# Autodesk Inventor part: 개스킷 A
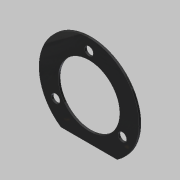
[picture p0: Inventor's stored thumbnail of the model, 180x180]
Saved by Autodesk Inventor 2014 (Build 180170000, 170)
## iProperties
Created: 2020-04
Part Number: 개스킷 A
Material: 고무
Document SubType Name: Modeling
Designer: mduedu
Density: 0.93 g/cm^3
Appearance: Rubber - Black - Version 1.1
Mass: 1.09963 g
Surface Area: 26.6928 cm^2
Volume: 1.18239 cm^3
Author: mduedu
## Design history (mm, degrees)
sketch "스케치1"
  geometry: C1 r 26 at (0, 0); 1 further point
  constraints: 1 centre point, 1 coincident
  dimensions: "d0" = 52 diameter of C1
extrude "돌출1" new body sketch "스케치1" distance "d1" = 1; taper "d2" = 0 deg
sketch "스케치2"
  geometry: L1 (-14.62, -21.5)-(14.62, -21.5); A1 r 26 centre (0, 0) between (-14.62, -21.5) and (14.62, -21.5) reference; 1 further point
  constraints: 2 end point, 2 point on circle, 1 horizontal
  dimensions: "d3" = 21.5 distance from line of L1 point (0, 0)
extrude "돌출2" cut sketch "스케치2" stored distance "d4" = 1; taper "d5" = 0 deg
sketch "스케치3" dims "d6" = 40
  geometry: 3 further points
  constraints: 2 vertical alignment, 1 coincident, 2 other
hole "구멍1" sketch "스케치3" at (0, 20) diameter "d7" = 4.5; stored, may be unused: countersink angle "d11" = 90 deg, drill point angle "d13" = 118 deg; dims "d8" = 6, "d9" = 4, "d10" = 2, "d12" = 8
sketch "스케치4"
  geometry: C1 r 16 at (0, 0); 1 further point
  constraints: 1 centre point, 1 coincident
  dimensions: "d17" = 32 diameter of C1
extrude "돌출3" cut sketch "스케치4" stored distance "d18" = 1; taper "d19" = 0 deg
node "솔리드1"
pattern_circular "원형 패턴1" dims angle "d15" = 360 deg
node "투영된 루프1"
